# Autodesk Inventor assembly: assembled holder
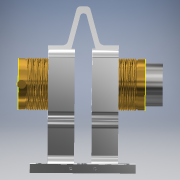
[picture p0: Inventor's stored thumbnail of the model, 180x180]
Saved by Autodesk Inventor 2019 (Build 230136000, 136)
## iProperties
Created: 2019-05
Part Number: assembled holder
Document SubType Name: Assembly
Designer: Chloe
Author: Chloe
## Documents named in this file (7)
- C:\Users\Chloe\Desktop\3d files\Magnet holder\Adobe Inventor format\Assembled magnet holder.iam
- C:\Users\Chloe\Desktop\3d files\Magnet holder\Adobe Inventor format\Magnet holder centrepiece.ipt
- C:\Users\Chloe\Desktop\3d files\Magnet holder\Adobe Inventor format\magnet holder.ipt
- C:\Users\Chloe\Desktop\3d files\Magnet holder\Adobe Inventor format\magnet retaining ring.ipt
- C:\Users\Chloe\Desktop\3d files\Magnet holder\Adobe Inventor format\magnet retaining ring handle.ipt
- C:\Users\Chloe\Desktop\3d files\Magnet holder\Adobe Inventor format\magnets support separator.ipt
- C:\Users\Chloe\Desktop\3d files\Magnet holder\Adobe Inventor format\NdFeB magnets.ipt
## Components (9 placed, 6 different names)
1. Magnet holder centrepiece:1 — Rigid:1, Rigid:2
2. magnet holder:1 — Rigid:2, Rigid:3
3. magnet holder:2 — Rigid:1, Cylindrical:2
4. magnet retaining ring:2 — Cylindrical:2, Cylindrical:5
5. magnet retaining ring handle:2 — Cylindrical:5
6. magnets support separator:1
7. magnet retaining ring:3 — Rigid:3, Cylindrical:6, Cylindrical:7
8. magnet retaining ring handle:3 — Cylindrical:6
9. NdFeB magnets:1 — Cylindrical:7
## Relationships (7: CylindricalJoint 4, WeldJoint 3)
- Rigid:1 [WeldJoint]: Magnet holder centrepiece:1 ↔ magnet holder:2
- Rigid:2 [WeldJoint]: Magnet holder centrepiece:1 ↔ magnet holder:1
- Cylindrical:2: magnet holder:2 ↔ magnet retaining ring:2
- Cylindrical:5: magnet retaining ring:2 ↔ magnet retaining ring handle:2
- Rigid:3 [WeldJoint]: magnet holder:1 ↔ magnet retaining ring:3
- Cylindrical:6: magnet retaining ring:3 ↔ magnet retaining ring handle:3
- Cylindrical:7: magnet retaining ring:3 ↔ NdFeB magnets:1
